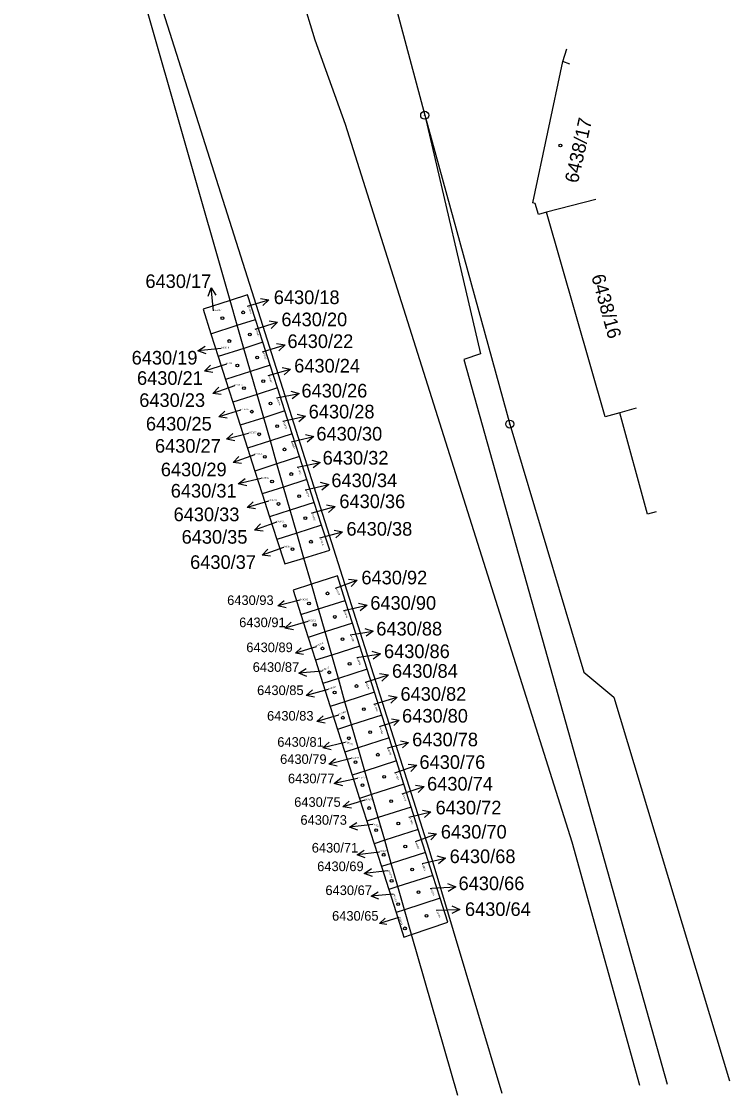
# Model space of a CAD drawing. Extents: x -825057 to -819383, y -1071633 to -1067888.
# Drawn here: x -822772.2 to -822683.8, y -1071124.6 to -1070990.4 of the extents above; entities that cross this region are included whole.
import ezdxf

# ---------------------------------------------------------------- set-up
doc = ezdxf.new("R2010")
doc.units = 0
for name, color, linetype in [('Vrstva 1', 7, 'Continuous'), ('Vrstva 10', 7, 'Continuous'), ('Vrstva 16', 7, 'Continuous'), ('Vrstva 19', 7, 'Continuous'), ('Vrstva 24', 7, 'Continuous'), ('Vrstva 25', 7, 'Continuous'), ('Vrstva 4', 7, 'Continuous')]:
    doc.layers.add(name, color=color, linetype=linetype)

msp = doc.modelspace()

# ---------------------------------------------------------------- linework, layer by layer
at = {"layer": 'Vrstva 1'}
for p, q in [((-822772.25, -1070933.41), (-822721.39, -1071093.76)), ((-822746.2, -1071025.23), (-822757.45, -1070985.89)), ((-822725.48, -1070988.75), (-822721.91, -1071002.11)), ((-822704.68, -1070995.4), (-822704.15, -1070993.8)), ((-822708.42, -1071013.05), (-822704.68, -1070995.4)), ((-822703.79, -1070995.71), (-822704.68, -1070995.4)), ((-822721.91, -1071002.11), (-822711.29, -1071040.68)), ((-822700.53, -1071012.61), (-822706.7, -1071014.23)), ((-822708.11, -1071013.13), (-822708.42, -1071013.05)), ((-822707.69, -1071014.51), (-822708.11, -1071013.13)), ((-822706.7, -1071014.23), (-822707.69, -1071014.51)), ((-822699.37, -1071039.76), (-822706.7, -1071014.23)), ((-822744.04, -1071024.54), (-822746.2, -1071025.23)), ((-822743.05, -1071027.6), (-822744.04, -1071024.54)), ((-822746.2, -1071025.23), (-822749.58, -1071026.32)), ((-822745.31, -1071028.33), (-822746.2, -1071025.23)), ((-822749.58, -1071026.32), (-822748.6, -1071029.39)), ((-822745.31, -1071028.33), (-822743.05, -1071027.6)), ((-822742.13, -1071030.47), (-822743.05, -1071027.6)), ((-822748.6, -1071029.39), (-822745.31, -1071028.33)), ((-822744.48, -1071031.23), (-822745.31, -1071028.33)), ((-822748.6, -1071029.39), (-822747.68, -1071032.26)), ((-822744.48, -1071031.23), (-822747.68, -1071032.26)), ((-822742.13, -1071030.47), (-822744.48, -1071031.23)), ((-822743.66, -1071034.1), (-822744.48, -1071031.23)), ((-822741.21, -1071033.31), (-822742.13, -1071030.47)), ((-822747.68, -1071032.26), (-822746.77, -1071035.1)), ((-822743.66, -1071034.1), (-822746.77, -1071035.1)), ((-822741.21, -1071033.31), (-822743.66, -1071034.1)), ((-822742.84, -1071036.98), (-822743.66, -1071034.1)), ((-822740.3, -1071036.16), (-822741.21, -1071033.31)), ((-822746.77, -1071035.1), (-822745.86, -1071037.95)), ((-822742.84, -1071036.98), (-822745.86, -1071037.95)), ((-822740.3, -1071036.16), (-822742.84, -1071036.98)), ((-822742, -1071039.89), (-822742.84, -1071036.98)), ((-822739.37, -1071039.04), (-822740.3, -1071036.16)), ((-822745.86, -1071037.95), (-822744.93, -1071040.83)), ((-822739.37, -1071039.04), (-822742, -1071039.89)), ((-822738.45, -1071041.89), (-822739.37, -1071039.04)), ((-822697.54, -1071039.26), (-822699.37, -1071039.76)), ((-822695.51, -1071038.71), (-822697.54, -1071039.26)), ((-822694.07, -1071051.95), (-822697.54, -1071039.26)), ((-822742, -1071039.89), (-822744.93, -1071040.83)), ((-822744.93, -1071040.83), (-822744.02, -1071043.68)), ((-822741.18, -1071042.77), (-822742, -1071039.89)), ((-822711.29, -1071040.68), (-822702.04, -1071071.68)), ((-822738.45, -1071041.89), (-822741.18, -1071042.77)), ((-822737.53, -1071044.75), (-822738.45, -1071041.89)), ((-822741.18, -1071042.77), (-822744.02, -1071043.68)), ((-822744.02, -1071043.68), (-822743.1, -1071046.55)), ((-822740.35, -1071045.66), (-822741.18, -1071042.77)), ((-822737.53, -1071044.75), (-822740.35, -1071045.66)), ((-822736.61, -1071047.61), (-822737.53, -1071044.75)), ((-822740.35, -1071045.66), (-822743.1, -1071046.55)), ((-822739.53, -1071048.55), (-822740.35, -1071045.66)), ((-822743.1, -1071046.55), (-822742.19, -1071049.41)), ((-822736.61, -1071047.61), (-822739.53, -1071048.55)), ((-822735.69, -1071050.46), (-822736.61, -1071047.61)), ((-822739.53, -1071048.55), (-822742.19, -1071049.41)), ((-822738.7, -1071051.43), (-822739.53, -1071048.55)), ((-822742.19, -1071049.41), (-822741.27, -1071052.26)), ((-822738.7, -1071051.43), (-822741.27, -1071052.26)), ((-822735.69, -1071050.46), (-822738.7, -1071051.43)), ((-822737.88, -1071054.29), (-822738.7, -1071051.43)), ((-822734.78, -1071053.29), (-822735.69, -1071050.46)), ((-822693.02, -1071051.66), (-822694.07, -1071051.95)), ((-822741.27, -1071052.26), (-822740.37, -1071055.09)), ((-822737.88, -1071054.29), (-822740.37, -1071055.09)), ((-822734.78, -1071053.29), (-822737.88, -1071054.29)), ((-822736.99, -1071057.41), (-822737.88, -1071054.29)), ((-822733.77, -1071056.41), (-822734.78, -1071053.29)), ((-822740.37, -1071055.09), (-822739.39, -1071058.15)), ((-822736.99, -1071057.41), (-822733.77, -1071056.41)), ((-822739.39, -1071058.15), (-822736.99, -1071057.41)), ((-822736.05, -1071060.69), (-822736.99, -1071057.41)), ((-822732.79, -1071059.65), (-822736.05, -1071060.69)), ((-822731.82, -1071062.7), (-822732.79, -1071059.65)), ((-822736.05, -1071060.69), (-822738.33, -1071061.41)), ((-822735.17, -1071063.77), (-822736.05, -1071060.69)), ((-822738.33, -1071061.41), (-822737.36, -1071064.46)), ((-822737.36, -1071064.46), (-822735.17, -1071063.77)), ((-822735.17, -1071063.77), (-822731.82, -1071062.7)), ((-822734.35, -1071066.65), (-822735.17, -1071063.77)), ((-822730.91, -1071065.55), (-822731.82, -1071062.7)), ((-822737.36, -1071064.46), (-822736.45, -1071067.32)), ((-822730.91, -1071065.55), (-822734.35, -1071066.65)), ((-822730.01, -1071068.41), (-822730.91, -1071065.55)), ((-822734.35, -1071066.65), (-822736.45, -1071067.32)), ((-822736.45, -1071067.32), (-822735.54, -1071070.18)), ((-822733.52, -1071069.53), (-822734.35, -1071066.65)), ((-822730.01, -1071068.41), (-822733.52, -1071069.53)), ((-822729.08, -1071071.3), (-822730.01, -1071068.41)), ((-822733.52, -1071069.53), (-822735.54, -1071070.18)), ((-822735.54, -1071070.18), (-822734.61, -1071073.07)), ((-822732.69, -1071072.45), (-822733.52, -1071069.53)), ((-822729.08, -1071071.3), (-822732.69, -1071072.45)), ((-822728.17, -1071074.17), (-822729.08, -1071071.3)), ((-822702.04, -1071071.68), (-822698.28, -1071074.78)), ((-822732.69, -1071072.45), (-822734.61, -1071073.07)), ((-822734.61, -1071073.07), (-822733.7, -1071075.95)), ((-822731.86, -1071075.36), (-822732.69, -1071072.45)), ((-822728.17, -1071074.17), (-822731.86, -1071075.36)), ((-822727.26, -1071077.03), (-822728.17, -1071074.17)), ((-822731.86, -1071075.36), (-822733.7, -1071075.95)), ((-822731.03, -1071078.25), (-822731.86, -1071075.36)), ((-822698.28, -1071074.78), (-822683.85, -1071122.7)), ((-822733.7, -1071075.95), (-822732.79, -1071078.81)), ((-822727.26, -1071077.03), (-822731.03, -1071078.25)), ((-822726.35, -1071079.89), (-822727.26, -1071077.03)), ((-822731.03, -1071078.25), (-822732.79, -1071078.81)), ((-822730.21, -1071081.13), (-822731.03, -1071078.25)), ((-822732.79, -1071078.81), (-822731.87, -1071081.67)), ((-822726.35, -1071079.89), (-822730.21, -1071081.13)), ((-822725.44, -1071082.75), (-822726.35, -1071079.89)), ((-822730.21, -1071081.13), (-822731.87, -1071081.67)), ((-822729.38, -1071084.02), (-822730.21, -1071081.13)), ((-822731.87, -1071081.67), (-822730.96, -1071084.52)), ((-822725.44, -1071082.75), (-822729.38, -1071084.02)), ((-822724.52, -1071085.65), (-822725.44, -1071082.75)), ((-822729.38, -1071084.02), (-822730.96, -1071084.52)), ((-822730.96, -1071084.52), (-822730.04, -1071087.43)), ((-822728.54, -1071086.95), (-822729.38, -1071084.02)), ((-822724.52, -1071085.65), (-822728.54, -1071086.95)), ((-822723.6, -1071088.52), (-822724.52, -1071085.65)), ((-822728.54, -1071086.95), (-822730.04, -1071087.43)), ((-822730.04, -1071087.43), (-822729.12, -1071090.29)), ((-822727.71, -1071089.84), (-822728.54, -1071086.95)), ((-822723.6, -1071088.52), (-822727.71, -1071089.84)), ((-822722.71, -1071091.33), (-822723.6, -1071088.52)), ((-822727.71, -1071089.84), (-822729.12, -1071090.29)), ((-822729.12, -1071090.29), (-822728.23, -1071093.1)), ((-822726.9, -1071092.67), (-822727.71, -1071089.84)), ((-822722.71, -1071091.33), (-822726.9, -1071092.67)), ((-822721.79, -1071094.19), (-822722.71, -1071091.33)), ((-822726.9, -1071092.67), (-822728.23, -1071093.1)), ((-822728.23, -1071093.1), (-822727.32, -1071095.96)), ((-822726.08, -1071095.56), (-822726.9, -1071092.67)), ((-822721.79, -1071094.19), (-822726.08, -1071095.56)), ((-822720.88, -1071097.06), (-822721.79, -1071094.19)), ((-822721.39, -1071093.76), (-822712.27, -1071124.25)), ((-822726.08, -1071095.56), (-822727.32, -1071095.96)), ((-822727.32, -1071095.96), (-822726.4, -1071098.82)), ((-822725.25, -1071098.45), (-822726.08, -1071095.56)), ((-822720.88, -1071097.06), (-822725.25, -1071098.45)), ((-822719.97, -1071099.91), (-822720.88, -1071097.06)), ((-822725.25, -1071098.45), (-822726.4, -1071098.82)), ((-822724.43, -1071101.34), (-822725.25, -1071098.45)), ((-822726.4, -1071098.82), (-822725.49, -1071101.68)), ((-822719.97, -1071099.91), (-822724.43, -1071101.34)), ((-822719.02, -1071102.91), (-822719.97, -1071099.91)), ((-822724.43, -1071101.34), (-822725.49, -1071101.68)), ((-822723.54, -1071104.42), (-822724.43, -1071101.34)), ((-822725.49, -1071101.68), (-822724.51, -1071104.75)), ((-822723.54, -1071104.42), (-822719.02, -1071102.91)), ((-822724.51, -1071104.75), (-822723.54, -1071104.42)), ((-822717.78, -1071124.55), (-822723.54, -1071104.42))]:
    msp.add_line(p, q, dxfattribs=at)
at = {"layer": 'Vrstva 10'}
for p, q in [((-822735.57, -1070992.74), (-822740.39, -1070976.74)), ((-822731.78, -1071003.26), (-822735.57, -1070992.74)), ((-822703.49, -1071092.91), (-822731.78, -1071003.26)), ((-822695.06, -1071123.31), (-822703.49, -1071092.91))]:
    msp.add_line(p, q, dxfattribs=at)
at = {"layer": 'Vrstva 16'}
for p, q in [((-822748.26, -1071026.54), (-822748.57, -1071023.677)), ((-822744.02, -1071025.96), (-822741.381, -1071025.15)), ((-822743.08, -1071028.82), (-822740.266, -1071027.969)), ((-822747.32, -1071031.23), (-822750.214, -1071031.539)), ((-822742.14, -1071031.67), (-822739.337, -1071030.782)), ((-822746.65, -1071033.19), (-822749.421, -1071034.08)), ((-822741.45, -1071034.61), (-822738.654, -1071033.804)), ((-822745.65, -1071035.9), (-822748.372, -1071036.841)), ((-822740.43, -1071037.42), (-822737.571, -1071036.88)), ((-822744.89, -1071038.94), (-822747.61, -1071039.79)), ((-822739.62, -1071040.32), (-822736.777, -1071039.701)), ((-822743.91, -1071041.84), (-822746.639, -1071042.552)), ((-822738.6, -1071042.91), (-822735.738, -1071042.239)), ((-822743.15, -1071044.52), (-822745.827, -1071045.499)), ((-822737.82, -1071046.06), (-822734.968, -1071045.482)), ((-822742.32, -1071047.49), (-822745.182, -1071048.161)), ((-822736.83, -1071048.88), (-822736.81, -1071048.88)), ((-822736.81, -1071048.88), (-822733.885, -1071048.213)), ((-822741.39, -1071050.3), (-822744.06, -1071051.11)), ((-822736.03, -1071051.78), (-822735.97, -1071051.76)), ((-822735.97, -1071051.76), (-822733.077, -1071050.966)), ((-822740.4, -1071052.94), (-822743.139, -1071053.923)), ((-822735.01, -1071054.88), (-822732.16, -1071054.16)), ((-822739.54, -1071056.09), (-822742.217, -1071057.069)), ((-822733.06, -1071061.17), (-822730.354, -1071060.185)), ((-822737.48, -1071062.69), (-822740.24, -1071063.4)), ((-822732.02, -1071063.98), (-822729.095, -1071063.313)), ((-822732.03, -1071063.98), (-822732.02, -1071063.98)), ((-822736.5, -1071065.32), (-822739.375, -1071066.177)), ((-822731.2, -1071067), (-822728.354, -1071066.561)), ((-822735.46, -1071068.51), (-822738.039, -1071069.31)), ((-822730.4, -1071069.85), (-822727.435, -1071069.396)), ((-822734.71, -1071071.54), (-822737.638, -1071071.8)), ((-822729.33, -1071072.91), (-822729.31, -1071072.9)), ((-822729.31, -1071072.9), (-822726.443, -1071072.017)), ((-822733.95, -1071073.85), (-822736.7, -1071074.597)), ((-822728.26, -1071075.67), (-822728.2, -1071075.65)), ((-822728.2, -1071075.65), (-822725.33, -1071074.778)), ((-822732.66, -1071077.05), (-822735.365, -1071077.848)), ((-822727.56, -1071078.45), (-822725.075, -1071077.652)), ((-822731.84, -1071080.46), (-822734.643, -1071081.121)), ((-822726.55, -1071081.12), (-822723.932, -1071080.46)), ((-822731.08, -1071082.46), (-822733.872, -1071083.168)), ((-822725.62, -1071084.24), (-822722.899, -1071083.296)), ((-822730.28, -1071084.95), (-822733.213, -1071085.579)), ((-822724.73, -1071086.86), (-822721.972, -1071085.931)), ((-822729.39, -1071087.66), (-822732.112, -1071088.504)), ((-822723.88, -1071089.79), (-822721.138, -1071089.132)), ((-822728.37, -1071090.68), (-822731.288, -1071091.039)), ((-822723.07, -1071092.82), (-822720.421, -1071091.854)), ((-822727.53, -1071094.14), (-822730.357, -1071094.498)), ((-822722.24, -1071095.57), (-822719.32, -1071094.883)), ((-822722.02, -1071096.01), (-822721.92, -1071095.99)), ((-822726.5, -1071096.47), (-822729.48, -1071096.815)), ((-822726.46, -1071096.46), (-822726.5, -1071096.47)), ((-822721.22, -1071098.68), (-822721.02, -1071098.67)), ((-822721.02, -1071098.67), (-822718.025, -1071098.502)), ((-822725.84, -1071099.39), (-822728.587, -1071099.66)), ((-822720.48, -1071101.4), (-822717.541, -1071101.31)), ((-822725.13, -1071102.32), (-822727.544, -1071103.044))]:
    msp.add_line(p, q, dxfattribs=at)
for points in [[(-822748.944, -1071024.683), (-822748.57, -1071023.677), (-822747.99, -1071024.579)], [(-822742.396, -1071024.981), (-822741.381, -1071025.15), (-822742.126, -1071025.86)], [(-822741.346, -1071027.784), (-822740.266, -1071027.969), (-822741.062, -1071028.722)], [(-822749.197, -1071031.918), (-822750.214, -1071031.539), (-822749.301, -1071030.954)], [(-822740.419, -1071030.611), (-822739.337, -1071030.782), (-822740.124, -1071031.545)], [(-822748.349, -1071034.245), (-822749.421, -1071034.08), (-822748.645, -1071033.322)], [(-822739.72, -1071033.607), (-822738.654, -1071033.804), (-822739.452, -1071034.539)], [(-822747.308, -1071036.981), (-822748.372, -1071036.841), (-822747.621, -1071036.073)], [(-822738.614, -1071036.583), (-822737.571, -1071036.88), (-822738.434, -1071037.537)], [(-822746.562, -1071039.96), (-822747.61, -1071039.79), (-822746.845, -1071039.053)], [(-822737.827, -1071039.434), (-822736.777, -1071039.701), (-822737.621, -1071040.382)], [(-822745.61, -1071042.77), (-822746.639, -1071042.552), (-822745.848, -1071041.86)], [(-822736.803, -1071041.986), (-822735.738, -1071042.239), (-822736.58, -1071042.94)], [(-822744.771, -1071045.619), (-822745.827, -1071045.499), (-822745.098, -1071044.726)], [(-822736.015, -1071045.199), (-822734.968, -1071045.482), (-822735.822, -1071046.15)], [(-822744.117, -1071048.414), (-822745.182, -1071048.161), (-822744.34, -1071047.46)], [(-822734.971, -1071047.948), (-822733.885, -1071048.213), (-822734.749, -1071048.923)], [(-822743.035, -1071051.285), (-822744.06, -1071051.11), (-822743.305, -1071050.395)], [(-822734.174, -1071050.748), (-822733.077, -1071050.966), (-822733.909, -1071051.713)], [(-822742.062, -1071054.052), (-822743.139, -1071053.923), (-822742.39, -1071053.139)], [(-822733.23, -1071053.925), (-822732.16, -1071054.16), (-822732.99, -1071054.875)], [(-822741.161, -1071057.189), (-822742.217, -1071057.069), (-822741.488, -1071056.296)], [(-822731.42, -1071060.062), (-822730.354, -1071060.185), (-822731.092, -1071060.964)], [(-822739.202, -1071063.623), (-822740.24, -1071063.4), (-822739.438, -1071062.703)], [(-822730.181, -1071063.048), (-822729.095, -1071063.313), (-822729.959, -1071064.023)], [(-822738.274, -1071066.371), (-822739.375, -1071066.177), (-822738.559, -1071065.412)], [(-822729.376, -1071066.233), (-822728.354, -1071066.561), (-822729.229, -1071067.181)], [(-822737.046, -1071069.473), (-822738.039, -1071069.31), (-822737.313, -1071068.613)], [(-822728.499, -1071069.053), (-822727.435, -1071069.396), (-822728.347, -1071070.042)], [(-822736.619, -1071072.201), (-822737.638, -1071071.8), (-822736.706, -1071071.225)], [(-822727.546, -1071071.834), (-822726.443, -1071072.017), (-822727.251, -1071072.789)], [(-822735.659, -1071074.807), (-822736.7, -1071074.597), (-822735.908, -1071073.89)], [(-822726.432, -1071074.59), (-822725.33, -1071074.778), (-822726.141, -1071075.547)], [(-822734.33, -1071078.033), (-822735.365, -1071077.848), (-822734.596, -1071077.131)], [(-822726.036, -1071077.504), (-822725.075, -1071077.652), (-822725.77, -1071078.332)], [(-822733.599, -1071081.368), (-822734.643, -1071081.121), (-822733.819, -1071080.433)], [(-822724.914, -1071080.244), (-822723.932, -1071080.46), (-822724.695, -1071081.117)], [(-822732.823, -1071083.397), (-822733.872, -1071083.168), (-822733.059, -1071082.467)], [(-822723.963, -1071083.157), (-822722.899, -1071083.296), (-822723.649, -1071084.064)], [(-822732.131, -1071085.858), (-822733.213, -1071085.579), (-822732.34, -1071084.881)], [(-822723.046, -1071085.781), (-822721.972, -1071085.931), (-822722.737, -1071086.7)], [(-822731.064, -1071088.676), (-822732.112, -1071088.504), (-822731.345, -1071087.769)], [(-822722.162, -1071088.894), (-822721.138, -1071089.132), (-822721.942, -1071089.808)], [(-822730.256, -1071091.405), (-822731.288, -1071091.039), (-822730.375, -1071090.433)], [(-822721.465, -1071091.734), (-822720.421, -1071091.854), (-822721.143, -1071092.617)], [(-822729.355, -1071094.85), (-822730.357, -1071094.498), (-822729.475, -1071093.908)], [(-822720.408, -1071094.626), (-822719.32, -1071094.883), (-822720.179, -1071095.599)], [(-822728.429, -1071097.197), (-822729.48, -1071096.815), (-822728.544, -1071096.204)], [(-822719.051, -1071098.058), (-822718.025, -1071098.502), (-822718.995, -1071099.057)], [(-822727.626, -1071100.028), (-822728.587, -1071099.66), (-822727.716, -1071099.112)], [(-822718.536, -1071100.85), (-822717.541, -1071101.31), (-822718.506, -1071101.83)], [(-822726.618, -1071103.205), (-822727.544, -1071103.044), (-822726.86, -1071102.4)]]:
    msp.add_lwpolyline(points, dxfattribs=at)
at = {"layer": 'Vrstva 24'}
for centre, radius in [((-822721.91, -1071002.11), 0.5), ((-822721.91, -1071002.11), 0.0327), ((-822711.29, -1071040.68), 0.5), ((-822711.29, -1071040.68), 0.0327)]:
    msp.add_circle(centre, radius, dxfattribs=at)
at = {"layer": 'Vrstva 25'}
for centre in [(-822704.97, -1071005.88), (-822747.17, -1071027.44), (-822744.57, -1071026.73), (-822746.3, -1071030.31), (-822743.73, -1071029.5), (-822742.83, -1071032.37), (-822745.3, -1071033.37), (-822742.06, -1071035.33), (-822744.47, -1071036.2), (-822741.16, -1071038.1), (-822743.5, -1071039.13), (-822740.32, -1071040.93), (-822742.57, -1071041.96), (-822739.42, -1071043.84), (-822741.87, -1071044.77), (-822740.97, -1071047.85), (-822738.56, -1071046.92), (-822737.59, -1071049.68), (-822740.16, -1071050.66), (-822736.81, -1071052.44), (-822739.37, -1071053.39), (-822736.11, -1071055.37), (-822738.41, -1071056.3), (-822734.05, -1071061.83), (-822736.36, -1071063.08), (-822733.13, -1071064.77), (-822735.64, -1071065.76), (-822732.18, -1071067.54), (-822734.66, -1071068.7), (-822731.28, -1071070.63), (-822733.82, -1071071.69), (-822730.41, -1071073.4), (-822733.15, -1071074.2), (-822732.12, -1071077.36), (-822729.51, -1071076.29), (-822731.38, -1071079.93), (-822728.71, -1071079.16), (-822727.77, -1071081.98), (-822730.54, -1071082.92), (-822726.97, -1071084.75), (-822729.67, -1071085.78), (-822726.1, -1071087.78), (-822728.83, -1071088.64), (-822725.2, -1071090.58), (-822727.97, -1071091.41), (-822724.33, -1071093.44), (-822727.03, -1071094.47), (-822723.48, -1071096.32), (-822726.04, -1071097.74), (-822722.67, -1071099.15), (-822725.23, -1071100.64), (-822721.69, -1071102.11), (-822724.37, -1071103.67)]:
    msp.add_circle(centre, 0.175, dxfattribs=at)
at = {"layer": 'Vrstva 4'}
for p, q in [((-822721.91, -1071002.11), (-822714.94, -1071031.91)), ((-822714.94, -1071031.91), (-822717.03, -1071032.62)), ((-822717.03, -1071032.62), (-822691.64, -1071123.13))]:
    msp.add_line(p, q, dxfattribs=at)

# ---------------------------------------------------------------- texts
at = {"layer": 'Vrstva 16'}
for s, height, p in [('6430/17', 1.7, (-822756.777, -1071023.68)), ('6430/18', 1.7, (-822740.75, -1071025.69)), ('6430/20', 1.7, (-822739.8, -1071028.46)), ('6430/22', 1.7, (-822739.04, -1071031.18)), ('6430/19', 1.7, (-822758.498, -1071033.24)), ('6430/24', 1.7, (-822738.2, -1071034.24)), ('6430/21', 1.7, (-822757.828, -1071035.78)), ('6430/26', 1.7, (-822737.29, -1071037.36)), ('6430/23', 1.7, (-822757.545, -1071038.54)), ('6430/28', 1.7, (-822736.39, -1071039.97)), ('6430/25', 1.7, (-822756.714, -1071041.49)), ('6430/30', 1.7, (-822735.43, -1071042.74)), ('6430/27', 1.7, (-822755.581, -1071044.25)), ('6430/32', 1.7, (-822734.65, -1071045.74)), ('6430/29', 1.7, (-822754.852, -1071047.2)), ('6430/34', 1.7, (-822733.56, -1071048.56)), ('6430/31', 1.7, (-822753.611, -1071049.86)), ('6430/36', 1.7, (-822732.56, -1071051.18)), ('6430/33', 1.7, (-822753.259, -1071052.81)), ('6430/38', 1.7, (-822731.68, -1071054.62)), ('6430/35', 1.7, (-822752.258, -1071055.62)), ('6430/37', 1.7, (-822751.194, -1071058.77)), ('6430/92', 1.7, (-822729.81, -1071060.7)), ('6430/93', 1.2, (-822746.57, -1071063.28)), ('6430/90', 1.7, (-822728.7, -1071063.87)), ('6430/91', 1.2, (-822745.07, -1071066.05)), ('6430/88', 1.7, (-822727.95, -1071067.09)), ('6430/89', 1.2, (-822744.18, -1071069.17)), ('6430/86', 1.7, (-822726.99, -1071069.91)), ('6430/87', 1.2, (-822743.38, -1071071.63)), ('6430/84', 1.7, (-822725.99, -1071072.37)), ('6430/85', 1.2, (-822742.83, -1071074.53)), ('6430/82', 1.7, (-822724.93, -1071075.24)), ('6430/83', 1.2, (-822741.59, -1071077.72)), ('6430/80', 1.7, (-822724.73, -1071077.97)), ('6430/81', 1.2, (-822740.31, -1071080.99)), ('6430/78', 1.7, (-822723.47, -1071080.93)), ('6430/79', 1.2, (-822739.96, -1071083.13)), ('6430/76', 1.7, (-822722.56, -1071083.75)), ('6430/77', 1.2, (-822738.98, -1071085.55)), ('6430/74', 1.7, (-822721.61, -1071086.46)), ('6430/75', 1.2, (-822738.2, -1071088.49)), ('6430/72', 1.7, (-822720.55, -1071089.43)), ('6430/73', 1.2, (-822737.42, -1071090.73)), ('6430/70', 1.7, (-822719.89, -1071092.46)), ('6430/71', 1.2, (-822736.01, -1071094.2)), ('6430/68', 1.7, (-822718.79, -1071095.52)), ('6430/69', 1.2, (-822735.33, -1071096.52)), ('6430/66', 1.7, (-822717.68, -1071098.9)), ('6430/67', 1.2, (-822734.3, -1071099.51)), ('6430/64', 1.7, (-822716.88, -1071102.12)), ('6430/65', 1.2, (-822733.47, -1071102.71))]:
    msp.add_text(s, height=height, dxfattribs=at).set_placement(p)
at = {"layer": 'Vrstva 19'}
for s, height, rotation, p in [('6438/17', 1.7, 77.4, (-822702.783, -1071010.668)), ('6438/16', 1.7, 285.3, (-822701.116, -1071022.214)), ('6430/18', 0.2, 288.4347, (-822744.02, -1071025.96)), ('6430/20', 0.2, 289.3761, (-822743.08, -1071028.82)), ('6430/22', 0.2, 288.1827, (-822742.14, -1071031.67)), ('6430/24', 0.2, 289.2384, (-822741.45, -1071034.61)), ('6430/26', 0.2, 290.4813, (-822740.43, -1071037.42)), ('6430/28', 0.2, 287.8308, (-822739.62, -1071040.32)), ('6430/30', 0.2, 290.5875, (-822738.6, -1071042.91)), ('6430/32', 0.2, 288.8262, (-822737.82, -1071046.06)), ('6430/34', 0.2, 291.51, (-822736.83, -1071048.88)), ('6430/36', 0.2, 287.7318, (-822736.04, -1071051.81)), ('6430/38', 0.2, 288.9738, (-822735.03, -1071054.9)), ('6430/92', 0.2, 292.1508, (-822733.06, -1071061.17)), ('6430/90', 0.2, 288.4815, (-822732.03, -1071063.98)), ('6430/88', 0.2, 292.6467, (-822731.23, -1071067.03)), ('6430/89', 0.2, 23.6106, (-822735.46, -1071068.51)), ('6430/86', 0.2, 289.053, (-822730.4, -1071069.85)), ('6430/87', 0.2, 22.3839, (-822734.71, -1071071.54)), ('6430/84', 0.2, 289.8945, (-822729.33, -1071072.91)), ('6430/85', 0.2, 14.9751, (-822733.95, -1071073.85)), ('6430/82', 0.2, 290.2158, (-822728.26, -1071075.67)), ('6430/83', 0.2, 21.2382, (-822732.66, -1071077.05)), ('6430/80', 0.2, 286.6527, (-822727.57, -1071078.48)), ('6430/81', 0.2, 339.5259, (-822731.84, -1071080.46)), ('6430/78', 0.2, 291.9249, (-822726.62, -1071081.1)), ('6430/76', 0.2, 287.9766, (-822725.62, -1071084.24)), ('6430/74', 0.2, 289.8324, (-822724.73, -1071086.86)), ('6430/73', 0.2, 333.5211, (-822728.37, -1071090.68)), ('6430/72', 0.2, 290.0124, (-822723.88, -1071089.79)), ('6430/70', 0.2, 291.4479, (-822723.12, -1071092.88)), ('6430/68', 0.2, 290.0016, (-822722.28, -1071095.6)), ('6430/69', 0.2, 289.2582, (-822726.46, -1071096.46)), ('6430/66', 0.2, 291.3705, (-822721.22, -1071098.68)), ('6430/67', 0.2, 284.0076, (-822725.84, -1071099.39)), ('6430/64', 0.2, 292.4703, (-822720.5, -1071101.44)), ('6430/65', 0.2, 287.0424, (-822725.13, -1071102.32))]:
    msp.add_text(s, height=height, rotation=rotation, dxfattribs=at).set_placement(p)
for s, p in [('6430/17', (-822748.26, -1071026.54)), ('6430/19', (-822747.32, -1071031.23)), ('6430/21', (-822746.65, -1071033.19)), ('6430/23', (-822745.65, -1071035.9)), ('6430/25', (-822744.89, -1071038.94)), ('6430/27', (-822743.91, -1071041.84)), ('6430/29', (-822743.15, -1071044.52)), ('6430/31', (-822742.32, -1071047.49)), ('6430/33', (-822741.39, -1071050.3)), ('6430/35', (-822740.4, -1071052.94)), ('6430/37', (-822739.54, -1071056.09)), ('6430/93', (-822737.48, -1071062.69)), ('6430/91', (-822736.5, -1071065.32)), ('6430/79', (-822731.08, -1071082.46)), ('6430/77', (-822730.28, -1071084.95)), ('6430/75', (-822729.39, -1071087.66)), ('6430/71', (-822727.53, -1071094.14))]:
    msp.add_text(s, height=0.2, dxfattribs=at).set_placement(p)

doc.saveas('drawing.dxf')
